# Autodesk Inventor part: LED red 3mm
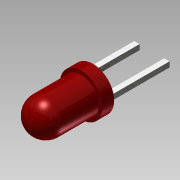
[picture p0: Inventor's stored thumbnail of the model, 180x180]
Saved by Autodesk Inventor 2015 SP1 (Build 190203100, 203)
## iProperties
Created: 2015-05
Part Number: LED red 3mm
Material: PC/ABS Plastic
Document SubType Name: Modeling
Designer: kazys
Density: 0.357273 g/cm^3
Appearance: Red
Author: kazys
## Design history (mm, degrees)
sketch "Sketch1"
  geometry: C1 r 1.8 at (0, 0); 1 further point
  constraints: 1 centre point, 1 coincident
  dimensions: "d0" = 3.6 diameter of C1
extrude "Extrusion1" new body sketch "Sketch1" distance "d1" = 1; taper "d2" = 0 deg
sketch "Sketch2"
  geometry: L1 (-1.5, 1)-(-1.5, 4); L2 (-1.8, 0)-(1.8, 0) reference; L3 (1.8, 1)-(-1.8, 1) reference; L4 (-1.8, 0)-(1.8, 0) reference; L5 (-1.5, 1)-(0, 1); L6 (1.8, 1)-(-1.8, 1) reference; L7 (0, 5.5)-(0, 1); L8 (0, 0)-(0, -0.856); A1 r 1.5 centre (0, 4) between (0, 5.5) and (-1.5, 4); 1 further point
  constraints: 8 end point, 4 midpoint, 3 vertical, 2 point on circle, 2 point on line, 1 centre point, 1 tangent, 1 vertical alignment
  dimensions: "d3" = 5.5 dimension on A1 L2; "d4" = 3 diameter of A1
revolve "Revolution1" sketch "Sketch2" stored, may be unused: angle "d5" = 90 deg
sketch "Sketch3"
  geometry: L1 (-1.495, 0.225)-(-1.045, 0.225); L2 (-1.045, 0.225)-(-1.045, -0.225); L3 (-1.045, -0.225)-(-1.495, -0.225); L4 (-1.495, -0.225)-(-1.495, 0.225); L5 (1.045, 0.225)-(1.495, 0.225); L6 (1.495, 0.225)-(1.495, -0.225); L7 (1.495, -0.225)-(1.045, -0.225); L8 (1.045, -0.225)-(1.045, 0.225); L9 (-1.495, 0.225)-(-1.045, -0.225); L10 (1.045, 0.225)-(1.495, -0.225); L11 (-1.27, 0)-(1.27, 0); 2 further points
  constraints: 22 end point, 5 parallel, 3 horizontal, 3 midpoint, 2 horizontal alignment, 2 perpendicular, 2 point on line, 1 coincident
  dimensions: "d6" = 2.54 distance of L11.end L11.start; "d7" = 0.45 distance of L3.end L1.start; "d8" = 0.45 distance of L1.start L1.end; "d9" = 0.45 distance of L5.start L5.end (derived)
extrude "Extrusion2" join sketch "Sketch3" distance "d10" = 5; taper "d11" = 0 deg
body "Solid1"
node "Projected Loop1"
